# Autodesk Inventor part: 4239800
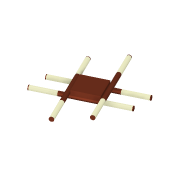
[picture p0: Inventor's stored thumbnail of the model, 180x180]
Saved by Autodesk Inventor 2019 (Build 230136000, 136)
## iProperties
Created: 2020-12
Part Number: 4239800
Material: Generic
Document SubType Name: Modeling
Designer: user
Density: 1 g/cm^3
Appearance: Default
Author: user
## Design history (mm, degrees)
sketch "Sketch1"
  geometry: L1 (-128.698, 37.718)-(51.341, 124.816); L2 (129.729, -37.219)-(-50.31, -124.317); L3 (-50.31, -124.317)-(-128.698, 37.718); L4 (129.729, -37.219)-(51.341, 124.816)
  constraints: 8 end point, 1 parallel
  dimensions: "d76" = 200 distance of L2.start L2.end; "d77" = 180 distance of L2.end L1.start
extrude "Extrusion1" new body sketch "Sketch1" distance "d33" = 40; taper "d34" = 0 deg
node "Sketch2"
workplane "Work Plane1"
sketch "Sketch3"
  geometry: C1 r 17.5 at (-22.5, 17.5); 1 further point
  constraints: 1 centre point
extrude "Extrusion2" join sketch "Sketch3" distance "d37" = 200; taper "d39" = 0 deg; dims "d38" = 100, "d40" = 0
sketch "Sketch4"
  geometry: C1 r 17.5 at (0, 0); 1 further point
  constraints: 1 centre point
extrude "Extrusion3" new body sketch "Sketch4" distance "d41" = 190; taper "d42" = 0 deg
sketch "Sketch5"
  geometry: C1 r 17.5 at (0, 0); 1 further point
  constraints: 1 centre point
extrude "Extrusion4" new body sketch "Sketch5" distance "d43" = 5; taper "d44" = 0 deg
sketch "Sketch6"
  geometry: L1 (-17.5, -17.5)-(-17.5, 22.5) reference; 3 further points
  constraints: 1 horizontal alignment, 2 other
extrude "Extrusion5" new body sketch "Sketch6" distance "d45" = 190; taper "d46" = 0 deg
sketch "Sketch7"
  geometry: C1 r 17.5 at (0, 0); 1 further point
  constraints: 1 centre point
extrude "Extrusion6" new body sketch "Sketch7" distance "d47" = 5; taper "d48" = 0 deg
workplane "Work Plane2"
node "Sketch8"
sketch "Sketch9"
  geometry: C1 r 17.5 at (22.5, -17.5); 2 further points
  constraints: 1 centre point
extrude "Extrusion7" join sketch "Sketch9" distance "d53" = 200; taper "d55" = 0 deg; dims "d54" = 100, "d56" = 0
node "Sketch10"
sketch "Sketch11"
  geometry: C1 r 17.5 at (0, 0); 1 further point
  constraints: 1 centre point
extrude "Extrusion8" new body sketch "Sketch11" distance "d57" = 190; taper "d58" = 0 deg
sketch "Sketch12"
  geometry: C1 r 17.5 at (0, 0); 1 further point
  constraints: 1 centre point
extrude "Extrusion9" new body sketch "Sketch12" distance "d59" = 5; taper "d60" = 0 deg
sketch "Sketch13"
  geometry: C1 r 17.5 at (0, 0); 1 further point
  constraints: 1 centre point
extrude "Extrusion10" new body sketch "Sketch13" distance "d61" = 190; taper "d62" = 0 deg
sketch "Sketch14"
  geometry: C1 r 17.5 at (0, 0); 1 further point
  constraints: 1 centre point
extrude "Extrusion11" new body sketch "Sketch14" distance "d63" = 5; taper "d64" = 0 deg
workplane "Work Plane3"
sketch "Sketch15"
  geometry: C1 r 17.5 at (17.5, -30.783); 1 further point
  constraints: 1 centre point
extrude "Extrusion12" new body sketch "Sketch15" distance "d66" = 180; taper "d68" = 0 deg; dims "d67" = 120, "d69" = 0
sketch "Sketch16"
  geometry: C1 r 17.5 at (0, 0); 1 further point
  constraints: 1 centre point
extrude "Extrusion13" new body sketch "Sketch16" distance "d70" = 190; taper "d71" = 0 deg
sketch "Sketch17"
  geometry: C1 r 17.5 at (0, 0); 1 further point
  constraints: 1 centre point
extrude "Extrusion14" new body sketch "Sketch17" distance "d72" = 190; taper "d73" = 0 deg
sketch "Sketch18"
  geometry: C1 r 17.5 at (0, 0); 1 further point
  constraints: 1 centre point
extrude "Extrusion15" new body sketch "Sketch18" distance "d74" = 5; taper "d75" = 0 deg
node "Sketch19"
feature "Move Body1"
feature "Move Body2"
sketch "Sketch20"
  geometry: C1 r 17.5 at (0, 0); 1 further point
  constraints: 1 centre point
extrude "Extrusion16" new body sketch "Sketch20" distance "d84" = 5; taper "d85" = 0 deg
workplane "Work Plane5"
sketch "Sketch21"
  geometry: C1 r 17.5 at (17.5, -162.5)
  constraints: 1 centre point
extrude "Extrusion17" new body sketch "Sketch21" distance "d90" = 120; taper "d92" = 0 deg; dims "d91" = 180, "d93" = 0
sketch "Sketch22"
  geometry: C1 r 17.5 at (0, 0); 1 further point
  constraints: 1 centre point
extrude "Extrusion18" new body sketch "Sketch22" distance "d94" = 190; taper "d95" = 0 deg
sketch "Sketch23"
  geometry: C1 r 17.5 at (0, 0); 1 further point
  constraints: 1 centre point
extrude "Extrusion19" new body sketch "Sketch23" distance "d96" = 5; taper "d97" = 0 deg
sketch "Sketch24"
  geometry: C1 r 17.5 at (0, 0); 1 further point
  constraints: 1 centre point
extrude "Extrusion20" new body sketch "Sketch24" distance "d98" = 190; taper "d99" = 0 deg
sketch "Sketch25"
  geometry: C1 r 17.5 at (0, 0); 1 further point
  constraints: 1 centre point
extrude "Extrusion21" new body sketch "Sketch25" distance "d100" = 5; taper "d101" = 0 deg
body "Solid1"
body "Solid2"
body "Solid3"
body "Solid4"
body "Solid5"
body "Solid6"
body "Solid7"
body "Solid8"
body "Solid9"
body "Solid10"
body "Solid11"
body "Solid12"
body "Solid13"
body "Solid14"
body "Solid15"
body "Solid16"
body "Solid17"
body "Solid18"
body "Solid19"
other parameters: "d78" = 0, "d79" = 0, "d80" = 13.283, "d81" = 0, "d82" = 0, "d83" = 13.283
